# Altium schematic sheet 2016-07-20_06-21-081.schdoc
size 181 x 111 mm; SheetNumber: 1; SheetTotal: 1
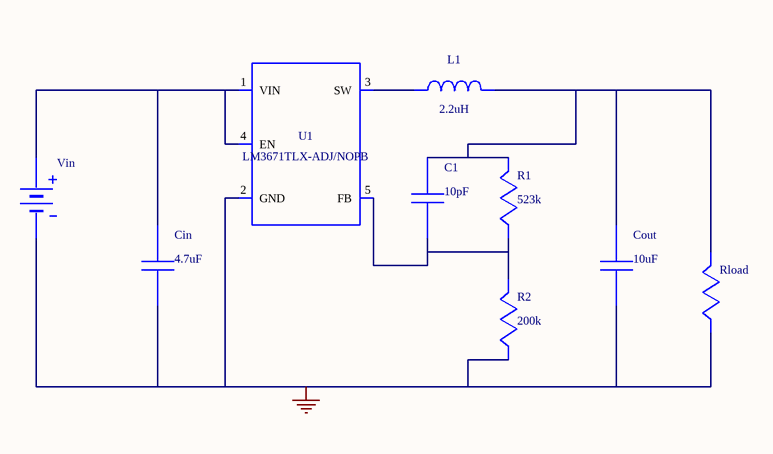
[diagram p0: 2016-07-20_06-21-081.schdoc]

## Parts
C1  value 10pF  (hidden comment: C0805C100M4GACTU)
Cin  value 4.7uF  (hidden comment: GRM188R60J475KE19D)
Cout  value 10uF  (hidden comment: GRM188R60J106ME47D)
L1  value 2.2uH  (hidden comment: MLP2520S2R2MT0S1)
R1  value 523k  (hidden comment: CRCW0402523KFKED)
R2  value 200k  (hidden comment: CRCW0402200KFKED)
Rload  WB_LOAD_RESISTOR  (value not drawn)
U1  LM3671TLX-ADJ/NOPB
Vin  WB_BATTERY  (value not drawn)

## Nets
0: Cin.2 Cout.2 R2.2 Rload.2 U1.2(GND) Vin.2(-)
NetC1_1: C1.1 Cout.1 L1.2 R1.1 Rload.1
NetC1_2: C1.2 R1.2 R2.1 U1.5(FB)
NetCin_1: Cin.1 U1.1(VIN) U1.4(EN) Vin.1(+)
NetL1_1: L1.1 U1.3(SW)

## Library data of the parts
C1 = C0805C100M4GACTU: Manufacturer Name: Kemet
Cin = GRM188R60J475KE19D: GRM188R60J475KE1; Manufacturer Name: MuRata
Cout = GRM188R60J106ME47D: GRM188R60J106ME4; Manufacturer Name: MuRata
L1 = MLP2520S2R2MT0S1: Unknown; Manufacturer Name: TDK
R1 = CRCW0402523KFKED: Manufacturer Name: Vishay-Dale
R2 = CRCW0402200KFKED: Manufacturer Name: Vishay-Dale
U1 = LM3671TLX-ADJ/NOPB: LM3671TLX-ADJ/NO; Manufacturer Name: Texas Instruments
